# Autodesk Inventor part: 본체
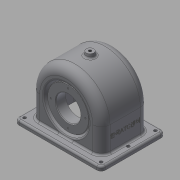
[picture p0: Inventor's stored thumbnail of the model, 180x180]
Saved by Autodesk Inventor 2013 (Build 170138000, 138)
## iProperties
Created: 2015-09
Part Number: 본체
Material: 일반
Document SubType Name: Modeling
Designer: Administrator
Density: 1 g/cm^3
Author: Administrator
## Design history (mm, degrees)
sketch "스케치1"
  geometry: L1 (-70, 52)-(70, 52); L2 (70, 52)-(70, -52); L3 (70, -52)-(-70, -52); L4 (-70, -52)-(-70, 52); L5 (-57, 38.5)-(57, 38.5); L6 (57, 38.5)-(57, -38.5); L7 (57, -38.5)-(-57, -38.5); L8 (-57, -38.5)-(-57, 38.5); 11 further points
  constraints: 16 end point, 6 midpoint, 4 parallel, 4 point on line, 3 horizontal alignment, 3 vertical alignment, 2 horizontal, 2 perpendicular
  dimensions: "d0" = 140 distance of L1.start L1.end; "d2" = 104 distance of L1.end L2.end; "d3" = 77 distance of L5.start L7.end; "d4" = 114 distance of L7.end L6.end
extrude "돌출2" join sketch "스케치1" distance "d8" = 47; taper "d9" = 0 deg
sketch "스케치2"
  geometry: L1 (-57, 0)-(57, 0) reference; L2 (-57, 0)-(-57, 47) reference; L3 (57, 47)-(-57, 47) reference; L4 (57, 0)-(57, 47) reference; L5 (-57, 47)-(57, 47); L6 (-51, 47)-(-51, 0); L7 (51, 47)-(51, 0); L8 (-51, 0)-(51, 0); A1 r 57 centre (0, 47) between (57, 47) and (-57, 47); A2 r 51 centre (0, 47) between (51, 47) and (-51, 47); 1 further point
  constraints: 8 end point, 5 point on line, 4 point on circle, 2 centre point, 2 collinear, 2 perpendicular, 2 tangent, 1 coincident, 1 midpoint
  dimensions: "d133" = 102 diameter of A2
  node "투영된 루프2"
extrude "돌출5" join sketch "스케치2" stored distance "d20" = 77; taper "d21" = 0 deg
extrude "돌출10" cut sketch "스케치2" stored distance "d136" = 67; taper "d137" = 0 deg
extrude "돌출4" join sketch "스케치1" distance "d16" = 7; taper "d17" = 0 deg
fillet "모깎기2" dims "d18" = 14
fillet "모깎기4" dims "d22" = 7
sketch "스케치4"
  geometry: L1 (63, -47)-(-63, -47) reference; C1 r 33 at (0, 0); A1 r 43 centre (0, 0) between (43, 0) and (-43, 0) reference; 1 further point
  constraints: 1 centre point, 1 coincident
  dimensions: "d25" = 66 diameter of C1
extrude "돌출6" cut sketch "스케치4" distance "d27" = 3; taper "d28" = 0 deg
sketch "스케치5"
  geometry: C1 r 33 at (0, 0) reference; C2 r 28 at (0, 0); 1 further point
  constraints: 1 centre point, 1 coincident
  dimensions: "d29" = 56 diameter of C2
extrude "돌출7" join sketch "스케치5" distance "d32" = 16; taper "d33" = 0 deg
hole "구멍1" diameter "d36" = 40; stored, may be unused: countersink angle "d40" = 90 deg, drill point angle "d42" = 0 deg; dims "d34" = 10, "d35" = 10, "d37" = 6, "d38" = 4, "d39" = 2, "d41" = 16
sketch "스케치6"
  geometry: C1 r 31 at (0, 0); A1 r 43 centre (0, 0) between (-43, 0) and (43, 0) reference; 1 further point
  constraints: 1 centre point, 1 coincident
  dimensions: "d43" = 62 diameter of C1
extrude "돌출8" join sketch "스케치6" distance "d45" = 10; taper "d46" = 0 deg
hole "구멍2" diameter "d49" = 40; stored, may be unused: countersink angle "d53" = 90 deg, drill point angle "d55" = 0 deg; dims "d47" = 10, "d48" = 10, "d50" = 6, "d51" = 4, "d52" = 2, "d54" = 16
sketch "스케치8"
  geometry: C1 r 20 at (0, 0) reference; 2 further points
  constraints: 1 vertical alignment
  dimensions: "d56" = 24 distance of point (0, -24) C1.centre
hole "구멍3" sketch "스케치8" at (0, -24) diameter "d57" = 2.459; stored, may be unused: countersink angle "d61" = 90 deg, drill point angle "d63" = 118 deg; dims "d58" = 6, "d59" = 4, "d60" = 2, "d62" = 8
node "작업 평면1"
sketch "스케치10"
  geometry: C1 r 6 at (0, 0); 1 further point
  constraints: 1 centre point, 1 coincident
  dimensions: "d79" = 12 diameter of C1
extrude "돌출9" join sketch "스케치10" stored distance "d81" = 10; taper "d82" = 10 deg
hole "구멍5" diameter "d85" = 4.459; stored, may be unused: countersink angle "d89" = 90 deg, drill point angle "d91" = 0 deg; dims "d83" = 10, "d84" = 10, "d86" = 15, "d87" = 4, "d88" = 2, "d90" = 15
sketch "스케치11"
  geometry: L1 (-33.5, 47)-(-24.5, 47) reference; L2 (-24.5, 47)-(-24.5, 47) reference; L3 (-33.5, 47)-(-24.5, 47) reference; L4 (-33.5, 47)-(-33.5, 47) reference; L5 (-38.5, 47)-(-24.5, 47) reference; L6 (-24.5, 47)-(-24.5, 47) reference; L7 (-38.5, 47)-(-24.5, 47) reference; L8 (-38.5, 47)-(-38.5, 47) reference; L9 (-19.5, 19)-(-19.5, 75) reference; L10 (-19.5, 75)-(-33.5, 86.747); L11 (-38.5, 84.416)-(-34.29, 80.883); L12 (-38.5, 47)-(-38.5, 90) reference; L13 (-35.5, 14)-(-35.5, 80) reference; L14 (-35.5, 80)-(-34.611, 80); L15 (-38.5, 80)-(-35.5, 80) reference; L16 (-38.5, 84.416)-(-38.5, 80); L17 (-35.5, 80)-(-38.5, 80); L18 (-33.5, 86.747)-(-33.5, 74.973); L19 (-33.5, 74.973)-(-19.5, 75); L20 (-38.5, 47)-(-19.5, 47); L21 (-33.5, 98)-(-33.5, 47) reference; A1 r 0.5 centre (-34.611, 80.5) between (-34.611, 80) and (-34.29, 80.883); 6 further points
  constraints: 16 end point, 2 collinear, 2 perpendicular, 2 point on circle, 2 tangent, 1 centre point, 1 midpoint, 1 point on line
  dimensions: "d92" = 50 deg angle of L9 L10; "d93" = 5 distance between parallel lines of L11 L10; "d95" = 0.5 radius of A1
  node "투영된 루프4"
  node "투영된 루프5"
revolve "회전1" stored, may be unused: angle "d96" = 90 deg
revolve "회전2" stored, may be unused: angle "d97" = 90 deg
sketch "스케치12"
  geometry: C1 r 20 at (0, 0) reference; 2 further points
  constraints: 1 vertical alignment
  dimensions: "d98" = 28 distance of C1.centre point (0, 28)
hole "구멍6" sketch "스케치12" at (0, 28) diameter "d99" = 2.459; stored, may be unused: countersink angle "d103" = 90 deg, drill point angle "d105" = 118 deg; dims "d100" = 7, "d101" = 4, "d102" = 2, "d104" = 9
chamfer "모따기1" distance "d106" = 1; stored, may be unused: second distance "d107" = 2, angle "d108" = 45 deg
sketch "스케치13"
  geometry: L1 (-70, 45)-(-70, -45) reference; L2 (-63, -52)-(63, -52) reference; 2 further points
  dimensions: "d109" = 8 distance from line of point (-62, -44) L2; "d110" = 8 distance from line of point (-62, -44) L1
hole "구멍7" sketch "스케치13" at (-62, -44) diameter "d111" = 5; stored, may be unused: countersink angle "d115" = 90 deg, drill point angle "d117" = 118 deg; dims "d112" = 7, "d113" = 4, "d114" = 2, "d116" = 9
sketch "스케치14"
  geometry: L1 (0, -14)-(40, -14) reference; L2 (47, 69.5)-(47, -20.5) reference; 2 further points
  constraints: 1 other
  dimensions: "d124" = 38.5 distance from line of point (17, 24.5) L1; "d125" = 30 distance from line of L2 point (17, 24.5)
feature "엠보싱1" sketch "스케치14" dims "d0" = 140, "d2" = 104, "d126" = 0.5, "d127" = 0
fillet "모깎기7" dims "d138" = 9
fillet "모깎기8" dims "d139" = 3
node "솔리드1"
pattern_circular "원형 패턴1" dims angle "d65" = 360 deg
pattern_linear "직사각형 패턴1" dims "d120" = 44, "d123" = 124
pattern_circular "원형 패턴3" dims angle "d131" = 360 deg
